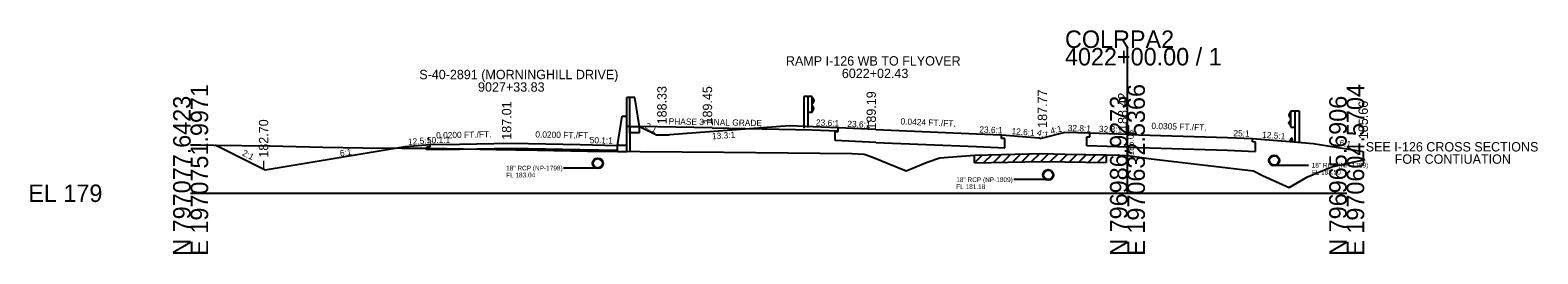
# Model space of a CAD drawing. Extents: x -26 to 1971083, y -10 to 798159.
# Drawn here: x 1170 to 1411.4, y -9.7 to 26.1 of the extents above; entities that cross this region are included whole.
import ezdxf

# ---------------------------------------------------------------- set-up
doc = ezdxf.new("R2010")
doc.units = 0
for name, color, linetype in [('RD_GPK_XS_Cell', 7, 'Continuous'), ('RD_XS_Base', 7, 'Continuous'), ('RD_XS_Box', 7, 'Continuous'), ('RD_XS_CurbTop', 7, 'Continuous'), ('RD_XS_EarthShd', 7, 'Continuous'), ('RD_XS_ExGround', 7, 'Continuous'), ('RD_XS_ExPaveRet', 7, 'Continuous'), ('RD_XS_GR', 7, 'Continuous'), ('RD_XS_MedBWall', 7, 'Continuous'), ('RD_XS_Misc_Line', 7, 'Continuous'), ('RD_XS_Pave', 7, 'Continuous'), ('RD_XS_PaveShd', 7, 'Continuous'), ('RD_XS_Pipe', 7, 'Continuous'), ('RD_XS_TieSlope', 7, 'Continuous'), ('RD_XS_TX_Elev_EX', 7, 'Continuous'), ('RD_XS_TX_Elev_PR', 7, 'Continuous'), ('RD_XS_TX_Misc', 7, 'Continuous'), ('RD_XS_TX_MkPT', 7, 'Continuous'), ('RD_XS_TX_Notes', 7, 'Continuous'), ('RD_XS_TX_Profile', 7, 'Continuous'), ('RD_XS_TX_ShdSlope', 7, 'Continuous'), ('RD_XS_TX_Slope', 7, 'Continuous'), ('RD_XS_TX_Station', 7, 'Continuous')]:
    doc.layers.add(name, color=color, linetype=linetype)

msp = doc.modelspace()

# ---------------------------------------------------------------- linework, layer by layer
at = {"layer": 'RD_GPK_XS_Cell'}
for p, q in [((1345.69, 0), (1345.69, 23.26)), ((1195.69, 0), (1345.69, 0)), ((1345.69, 0), (1380.8, 0))]:
    msp.add_line(p, q, dxfattribs=at)
at = {"layer": 'RD_XS_Base'}
for p, q in [((1267.54, 10.38), (1267.54, 10.68)), ((1298.88, 9.91), (1299.38, 9.89)), ((1298.88, 8.43), (1298.88, 9.91)), ((1299.38, 9.89), (1299.38, 10.45)), ((1233.53, 7.44), (1234.03, 7.45)), ((1233.53, 6.96), (1233.53, 7.44)), ((1234.03, 7.45), (1234.03, 7.75)), ((1264.06, 7.37), (1264.06, 7.67)), ((1305.42, 8.15), (1298.88, 8.43)), ((1305.42, 8.15), (1321.51, 7.46)), ((1321.51, 7.46), (1326.04, 7.27)), ((1325.54, 8.77), (1325.54, 9.33)), ((1326.04, 8.75), (1325.54, 8.77)), ((1326.04, 7.27), (1326.04, 8.75)), ((1339.19, 9.06), (1339.69, 9.04)), ((1339.19, 7.58), (1339.19, 9.06)), ((1345.69, 7.38), (1339.19, 7.58)), ((1339.69, 9.04), (1339.69, 9.6)), ((1345.69, 7.38), (1361.69, 6.89)), ((1365.69, 8.21), (1365.69, 8.77)), ((1366.19, 8.19), (1365.69, 8.21)), ((1366.19, 6.71), (1366.19, 8.19)), ((1236.03, 7.01), (1233.53, 6.96)), ((1236.03, 7.01), (1247.04, 7.23)), ((1247.04, 7.23), (1258.05, 7.01)), ((1258.05, 7.01), (1264.06, 6.89)), ((1361.69, 6.89), (1366.19, 6.71))]:
    msp.add_line(p, q, dxfattribs=at)
at = {"layer": 'RD_XS_Box'}
for p, q in [((1266.04, 15.35), (1265.56, 15.35)), ((1265.56, 12.34), (1265.56, 15.35)), ((1266.04, 10.71), (1265.56, 10.71)), ((1266.04, 10.71), (1266.04, 6.69))]:
    msp.add_line(p, q, dxfattribs=at)
at = {"layer": 'RD_XS_CurbTop'}
for p, q in [((1371.69, 8.29), (1371.94, 8.75)), ((1371.69, 8.29), (1372.15, 8.25)), ((1372.15, 8.25), (1372.09, 8.69))]:
    msp.add_line(p, q, dxfattribs=at)
msp.add_ellipse((1372.01, 8.67), major_axis=(0, -0.131), ratio=0.686, start_param=1.762783, end_param=4.036677, dxfattribs=at)
at = {"layer": 'RD_XS_EarthShd'}
for p, q in [((1299.38, 10.45), (1295.36, 10.62)), ((1339.69, 9.6), (1335.69, 9.73)), ((1234.03, 7.75), (1230.03, 7.43)), ((1325.54, 9.33), (1331.57, 8.85)), ((1365.69, 8.77), (1371.69, 8.29))]:
    msp.add_line(p, q, dxfattribs=at)
at = {"layer": 'RD_XS_ExGround'}
msp.add_line((1380.8, 4.75), (1383.76, 5.41), dxfattribs=at)
msp.add_lwpolyline([(1195.69, 7.75), (1197.28, 7.75), (1199.42, 7.69), (1208.32, 7.61), (1216.84, 7.36), (1223.31, 7.26), (1229.53, 7.24), (1234.11, 7.2), (1244.61, 7), (1245.23, 6.99), (1247.74, 6.94), (1248.45, 6.93), (1259.22, 6.74), (1260.98, 6.72), (1281.07, 6.57), (1301.55, 6.35), (1303.56, 6.27), (1304.75, 5.83), (1310.25, 3.61), (1313.63, 5), (1315.63, 5.68), (1321.2, 6.12), (1332.01, 6.34), (1335.72, 6.26), (1342.3, 6.16), (1344.46, 6.09), (1345.73, 6.05), (1349.49, 5.53), (1365.9, 3.57), (1367.31, 2.85), (1371.59, 0.92), (1374.54, 2.62), (1378.42, 4.22), (1380.8, 4.75)], dxfattribs=at)
at = {"layer": 'RD_XS_ExPaveRet'}
for p, q in [((1321.2, 4.87), (1321.2, 6.12)), ((1321.2, 4.87), (1332.01, 5.09)), ((1332.01, 5.09), (1335.72, 5.01)), ((1335.72, 5.01), (1342.3, 4.91)), ((1342.3, 6.16), (1342.3, 4.91))]:
    msp.add_line(p, q, dxfattribs=at)
at = {"layer": 'RD_XS_GR'}
for p, q in [((1294.54, 15.49), (1293.87, 15.49)), ((1293.87, 15.49), (1293.87, 10.44)), ((1295.2, 15.49), (1294.54, 15.49)), ((1294.54, 15.49), (1294.54, 10.55)), ((1295.2, 12.92), (1295.2, 15.49)), ((1295.2, 15.33), (1295.47, 14.89)), ((1295.47, 14.78), (1295.2, 14.34)), ((1295.47, 14.89), (1295.47, 14.78)), ((1295.2, 12.92), (1294.54, 12.92)), ((1295.47, 13.63), (1295.2, 14.07)), ((1295.2, 13.08), (1295.47, 13.52)), ((1295.47, 13.52), (1295.47, 13.63)), ((1371.83, 13.01), (1371.56, 12.57)), ((1371.56, 12.57), (1371.56, 12.46)), ((1371.56, 12.46), (1371.83, 12.02)), ((1371.83, 13.17), (1372.5, 13.17)), ((1371.83, 10.6), (1371.83, 13.17)), ((1372.5, 13.17), (1373.17, 13.17)), ((1372.5, 13.17), (1372.5, 8.22)), ((1373.17, 13.17), (1373.17, 8.11)), ((1371.56, 11.31), (1371.83, 11.75)), ((1371.56, 11.2), (1371.56, 11.31)), ((1371.83, 10.76), (1371.56, 11.2)), ((1371.83, 10.6), (1372.5, 10.6))]:
    msp.add_line(p, q, dxfattribs=at)
at = {"layer": 'RD_XS_MedBWall'}
for p, q in [((1266.04, 9.7), (1266.04, 15.35)), ((1266.79, 15.35), (1266.04, 15.35)), ((1267.54, 10.68), (1266.79, 15.35)), ((1264.06, 7.67), (1264.81, 12.34)), ((1264.81, 12.34), (1265.56, 12.34)), ((1265.56, 6.69), (1265.56, 12.34)), ((1266.04, 10.68), (1267.54, 10.68)), ((1267.54, 9.68), (1266.04, 9.68)), ((1267.54, 9.68), (1267.54, 10.68)), ((1265.56, 7.67), (1264.06, 7.67)), ((1264.06, 6.67), (1264.06, 7.67)), ((1264.06, 6.67), (1265.56, 6.67))]:
    msp.add_line(p, q, dxfattribs=at)
at = {"layer": 'RD_XS_Misc_Line'}
for p, q in [((1321.2, 4.87), (1322.49, 6.15)), ((1322.72, 4.9), (1324.01, 6.18)), ((1324.24, 4.93), (1325.53, 6.21)), ((1325.75, 4.96), (1327.04, 6.24)), ((1327.27, 4.99), (1328.56, 6.27)), ((1328.79, 5.02), (1330.08, 6.3)), ((1330.3, 5.05), (1331.59, 6.33)), ((1331.82, 5.08), (1333.07, 6.32)), ((1333.34, 5.06), (1334.58, 6.29)), ((1334.85, 5.03), (1336.09, 6.26)), ((1336.37, 5), (1337.61, 6.23)), ((1337.89, 4.98), (1339.13, 6.21)), ((1339.4, 4.95), (1340.65, 6.18)), ((1340.92, 4.93), (1342.17, 6.16))]:
    msp.add_line(p, q, dxfattribs=at)
at = {"layer": 'RD_XS_Pave'}
for p, q in [((1279.19, 10.45), (1295.21, 10.14)), ((1305.42, 10.19), (1321.51, 9.5)), ((1236.03, 7.79), (1247.04, 8.01)), ((1247.04, 8.01), (1258.05, 7.79)), ((1345.69, 9.42), (1361.69, 8.93))]:
    msp.add_line(p, q, dxfattribs=at)
at = {"layer": 'RD_XS_PaveShd'}
for p, q in [((1279.19, 10.45), (1267.54, 10.68)), ((1295.21, 10.14), (1299.22, 9.98)), ((1305.42, 10.19), (1299.38, 10.45)), ((1236.03, 7.79), (1234.03, 7.75)), ((1258.05, 7.79), (1264.06, 7.67)), ((1321.51, 9.5), (1325.54, 9.33)), ((1345.69, 9.42), (1339.69, 9.6)), ((1361.69, 8.93), (1365.69, 8.77))]:
    msp.add_line(p, q, dxfattribs=at)
at = {"layer": 'RD_XS_Pipe'}
for p, q in [((1260.38, 4.04), (1255.38, 4.04)), ((1369.69, 4.5), (1374.69, 4.5)), ((1332.51, 2.18), (1327.51, 2.18))]:
    msp.add_line(p, q, dxfattribs=at)
for centre, radius in [((1260.88, 4.79), 0.85), ((1260.88, 4.79), 0.75), ((1369.19, 5.25), 0.85), ((1369.19, 5.25), 0.75), ((1333.01, 2.93), 0.85), ((1333.01, 2.93), 0.75)]:
    msp.add_circle(centre, radius, dxfattribs=at)
at = {"layer": 'RD_XS_TieSlope'}
for p, q in [((1267.54, 10.68), (1270.26, 9.33)), ((1291.58, 10.77), (1272.36, 9.33)), ((1295.36, 10.62), (1291.58, 10.77)), ((1335.69, 9.73), (1331.88, 8.77)), ((1207.63, 3.7), (1199.63, 7.69)), ((1230.03, 7.43), (1207.63, 3.7)), ((1270.26, 9.33), (1272.36, 9.33)), ((1331.57, 8.85), (1331.88, 8.77)), ((1371.69, 8.29), (1375.44, 7.99)), ((1375.44, 7.99), (1383.44, 6.66)), ((1383.44, 6.66), (1383.44, 5.34))]:
    msp.add_line(p, q, dxfattribs=at)

# ---------------------------------------------------------------- texts
at = {"layer": 'RD_GPK_XS_Cell'}
for s, p in [('COLRPA2', (1335.69, 23.26)), ('4022+00.00 / 1', (1335.69, 20.46)), ('EL 179', (1169.69, -1.4))]:
    msp.add_text(s, height=2.8, dxfattribs=at).set_placement(p)
for s, p in [('E 1970751.9971', (1198.49, -10)), ('E 1970632.5366', (1348.49, -10)), ('E 1970604.5704', (1383.6, -10)), ('N 797077.6423', (1195.69, -10)), ('N 796986.9273', (1345.69, -10)), ('N 796965.6906', (1380.8, -10))]:
    msp.add_text(s, height=2.8, rotation=90, dxfattribs=at).set_placement(p)
at = {"layer": 'RD_XS_Pipe'}
for s, p in [('18" RCP (NP-1789)', (1375.19, 4.12)), ('18" RCP (NP-1798)', (1246.2, 3.66)), ('FL 183.04', (1246.2, 2.54)), ('18" RCP (NP-1809)', (1318.28, 1.8)), ('FL 183.50', (1375.19, 3)), ('FL 181.18', (1318.28, 0.68))]:
    msp.add_text(s, height=0.75, dxfattribs=at).set_placement(p)
at = {"layer": 'RD_XS_TX_Elev_EX'}
msp.add_text('185.05', height=1, rotation=90, dxfattribs=at).set_placement((1346.69, 6.05))
at = {"layer": 'RD_XS_TX_Elev_PR'}
for s, p in [(' 189.45', (1279.19, 10.45)), (' 187.01', (1247.04, 8.01)), ('189.19', (1305.42, 10.19)), (' 188.42', (1345.69, 9.42))]:
    msp.add_text(s, height=1.5, rotation=90, dxfattribs=at).set_placement(p)
at = {"layer": 'RD_XS_TX_Misc'}
for s, p in [('188.33', (1271.9, 11.03)), ('187.77', (1332.83, 10.47)), ('185.66', (1384.19, 8.66)), ('182.70', (1208.12, 5.7))]:
    msp.add_text(s, height=1.5, rotation=90, dxfattribs=at).set_placement(p)
at = {"layer": 'RD_XS_TX_MkPT'}
msp.add_text('L', height=1.5, dxfattribs=at).set_placement((1207.12, 3.7))
at = {"layer": 'RD_XS_TX_Notes'}
for s, p in [('SEE I-126 CROSS SECTIONS', (1383.85, 6.69)), ('FOR CONTIUATION', (1388.48, 4.72))]:
    msp.add_text(s, height=1.5, dxfattribs=at).set_placement(p)
at = {"layer": 'RD_XS_TX_Profile'}
for rotation, p in [(1.1432, (1233.54, 7.99)), (358.8559, (1259.58, 8.01))]:
    msp.add_text('50.1:1', height=1, rotation=rotation, dxfattribs=at).set_placement(p)
at = {"layer": 'RD_XS_TX_ShdSlope'}
for s, rotation, p in [('PHASE 3 FINAL GRADE', 358.9078, (1272.23, 11.02)), ('23.6:1', 357.5718, (1295.8, 10.85)), ('12.6:1', 355.4533, (1327.1, 9.46)), ('32.8:1', 358.2525, (1336.12, 9.96)), ('12.5:1', 355.4261, (1367.23, 8.9)), ('12.5:1', 4.5697, (1230.53, 7.72))]:
    msp.add_text(s, height=1, rotation=rotation, dxfattribs=at).set_placement(p)
at = {"layer": 'RD_XS_TX_Slope'}
for s, rotation, p in [('0.0200 FT./FT.', 1.1432, (1235.01, 8.77)), ('0.0200 FT./FT.', 358.8559, (1250.88, 8.93)), ('2:1', 333.5723, (1268.38, 10.47)), ('13.3:1', 4.2892, (1279.21, 8.62)), ('23.6:1', 357.5718, (1300.83, 10.63)), ('0.0424 FT./FT.', 357.5718, (1309.34, 11.02)), ('23.6:1', 357.5718, (1321.96, 9.73)), ('4:1', 346.0445, (1331.13, 9.27)), ('4:1', 14.0362, (1333.48, 9.45)), ('32.8:1', 358.2525, (1341.12, 9.81)), ('0.0305 FT./FT.', 358.2525, (1349.52, 10.3)), ('25:1', 357.7094, (1362.64, 9.14)), ('6:1', 350.5377, (1379.57, 7.62)), ('2:1', 333.4561, (1203.85, 6.11)), ('6:1', 9.4537, (1219.67, 5.88))]:
    msp.add_text(s, height=1, rotation=rotation, dxfattribs=at).set_placement(p)
at = {"layer": 'RD_XS_TX_Station'}
for s, p in [('RAMP I-126 WB TO FLYOVER', (1291.01, 20.44)), ('S-40-2891 (MORNINGHILL DRIVE)', (1232.3, 18.26)), ('6022+02.43', (1299.96, 18.44)), ('9027+33.83', (1241.71, 16.26))]:
    msp.add_text(s, height=1.5, dxfattribs=at).set_placement(p)

doc.saveas('drawing.dxf')
